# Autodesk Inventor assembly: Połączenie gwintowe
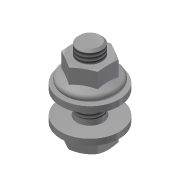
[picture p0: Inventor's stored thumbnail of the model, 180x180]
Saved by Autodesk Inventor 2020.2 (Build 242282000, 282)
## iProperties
Manager: www.cadconsulting.pl
Company: Fabian Stasiak CAD Consulting
ClientObjectVersion: 1
Created: 2011-01
Part Number: Połączenie gwintowe
Document SubType Name: Assembly
Designer: F.Stasiak
Author: F.Stasiak
Subject: Zbiór ćwiczeń. Autodesk Inventor 2020. Kurs podstawowy
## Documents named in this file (4)
- C:\2020_Kurs_podstawowy\R6 Zespoły\Kolizja\100-000\Design Accelerator\Połączenie gwintowe4.iam
- C:\2020_Kurs_podstawowy\Zasoby\Content Center Files\pl-PL\DIN 6796\DIN 6796 - 12.ipt
- C:\2020_Kurs_podstawowy\Zasoby\Content Center Files\pl-PL\DIN EN 24 017\ISO 4017 - M12 x 35DIN EN.ipt
- C:\2020_Kurs_podstawowy\Zasoby\Content Center Files\pl-PL\DIN 6923\DIN 6923 - M12 x 1,75.ipt
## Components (4 placed, 3 different names)
1. DIN 6796 12:1
2. DIN EN 24017 M12 x 35:1
3. DIN 6796 12:2
4. DIN 6923 M12:1
